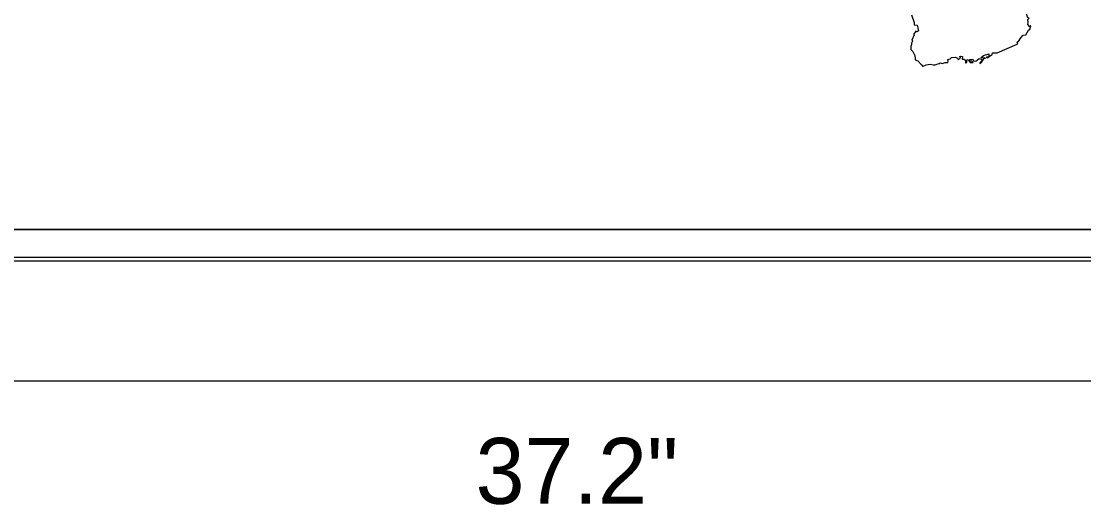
# Model space of a CAD drawing. Extents: x 0 to 770, y 0 to 495.
# Drawn here: x 643.3 to 699.7, y 10 to 35.6 of the extents above; entities that cross this region are included whole.
import ezdxf

# ---------------------------------------------------------------- set-up
doc = ezdxf.new("R2010")
doc.units = 0
for name, color, linetype in [('GSBWFill', 7, 'Continuous'), ('GSColorFill', 7, 'Continuous'), ('GSDims', 7, 'Continuous'), ('GSOutline', 7, 'Continuous'), ('SupstrConc', 7, 'Continuous')]:
    doc.layers.add(name, color=color, linetype=linetype)

msp = doc.modelspace()

# ---------------------------------------------------------------- linework, layer by layer
at = {"layer": 'GSBWFill'}
for p, q in [((716.157, 24.585), (626.399, 24.585)), ((626.399, 22.923), (716.157, 22.923))]:
    msp.add_line(p, q, dxfattribs=at)
at = {"layer": 'GSColorFill'}
for p, q in [((716.157, 24.585), (626.399, 24.585)), ((626.382, 22.923), (716.157, 22.923)), ((716.157, 23.089), (626.384, 23.089)), ((626.384, 22.923), (716.157, 22.923)), ((626.399, 22.923), (716.157, 22.923))]:
    msp.add_line(p, q, dxfattribs=at)
at = {"layer": 'GSDims'}
msp.add_line((633.863, 16.542), (707.097, 16.542), dxfattribs=at)
at = {"layer": 'GSOutline'}
for p, q in [((626.382, 24.585), (716.157, 24.585)), ((626.382, 22.923), (716.157, 22.923))]:
    msp.add_line(p, q, dxfattribs=at)
at = {"layer": 'SupstrConc'}
for points in [[(696.771, 35.581), (696.755, 35.736), (696.825, 35.807), (696.755, 35.83), (696.677, 36.033), (696.701, 36.446), (696.81, 36.633), (696.942, 36.874), (696.903, 37.202), (696.958, 37.35), (697.067, 37.42), (697.09, 37.365), (697.16, 37.474), (697.379, 37.965), (697.34, 38.098), (697.784, 38.448), (697.838, 39.087), (697.932, 39.352), (698.277, 39.69)], [(690.583, 35.978), (690.716, 35.581), (690.716, 35.448), (690.879, 35.433), (690.949, 35.136), (690.879, 35.074), (690.801, 35.113), (690.677, 34.949)], [(695.126, 33.967), (696.186, 34.419), (696.225, 34.458), (696.186, 34.497), (696.225, 34.583), (696.264, 34.568), (696.373, 34.77), (696.514, 34.91), (696.646, 34.926), (696.794, 35.168), (696.864, 35.222), (696.919, 35.394), (696.903, 35.409), (696.864, 35.355), (696.755, 35.464), (696.771, 35.581)], [(690.677, 34.949), (690.716, 34.926), (690.599, 34.645), (690.622, 34.583), (690.583, 34.474), (690.583, 34.404), (690.544, 34.31), (690.544, 34.139), (690.638, 34.038), (690.747, 33.819), (690.77, 33.671), (690.77, 33.593), (690.918, 33.539), (691.105, 33.328), (691.16, 33.25), (691.191, 33.25), (691.355, 33.328), (691.573, 33.367), (691.721, 33.328), (691.838, 33.328), (692.025, 33.406), (692.064, 33.391), (692.064, 33.406), (692.103, 33.43), (692.196, 33.406), (692.36, 33.461), (692.508, 33.461), (692.531, 33.523), (692.508, 33.617), (692.625, 33.648), (692.695, 33.726), (692.905, 33.741), (693.022, 33.687), (693.053, 33.617), (693.186, 33.687), (693.147, 33.765), (693.186, 33.796), (693.279, 33.765), (693.264, 33.632)], [(693.264, 33.632), (693.389, 33.632), (693.443, 33.523), (693.466, 33.461), (693.428, 33.43), (693.49, 33.445), (693.513, 33.461), (693.513, 33.5), (693.49, 33.554), (693.513, 33.617), (693.607, 33.578), (693.692, 33.445), (693.848, 33.461), (693.786, 33.523), (693.692, 33.523), (693.661, 33.617), (693.825, 33.632), (693.848, 33.593), (693.864, 33.539), (693.996, 33.523), (694.16, 33.671), (694.316, 33.632), (694.332, 33.578), (694.199, 33.43), (694.199, 33.406), (694.316, 33.484), (694.37, 33.554), (694.394, 33.648), (694.464, 33.687), (694.503, 33.687), (694.448, 33.702), (694.3, 33.687), (694.277, 33.726), (694.394, 33.819), (694.69, 33.913), (694.69, 33.835), (694.667, 33.741), (694.558, 33.741), (694.558, 33.726), (694.635, 33.702), (694.706, 33.765), (694.854, 33.874), (694.877, 33.967), (695.126, 33.967)]]:
    msp.add_lwpolyline(points, dxfattribs=at)

# ---------------------------------------------------------------- texts
at = {"layer": 'GSDims'}
msp.add_text('37.2"', height=3.5, dxfattribs=at).set_placement((667.421, 10.003))

doc.saveas('drawing.dxf')
